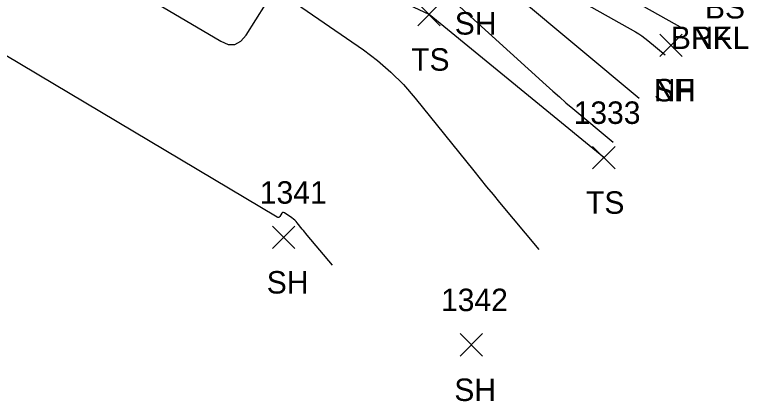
# Model space of a CAD drawing. Extents: x 1592612 to 1596497, y 111838 to 113741.
# Drawn here: x 1592923.4 to 1592988.7, y 113203.6 to 113238 of the extents above; entities that cross this region are included whole.
import ezdxf

# ---------------------------------------------------------------- set-up
doc = ezdxf.new("R2010")
doc.units = 0
for name, color, linetype in [('L_A', 7, 'Continuous'), ('L_I', 7, 'Continuous'), ('L_TIC', 7, 'Continuous'), ('LELB', 7, 'Continuous'), ('LSOGCMA', 7, 'Continuous'), ('LSOGCMI', 7, 'Continuous')]:
    doc.layers.add(name, color=color, linetype=linetype)

msp = doc.modelspace()

# ---------------------------------------------------------------- linework, layer by layer
at = {"layer": 'L_TIC'}
for points in [[(1592959.292, 113236.985), (1592961.292, 113238.985)], [(1592961.292, 113236.985), (1592959.292, 113238.985)], [(1592980.827, 113234.253), (1592982.827, 113236.253)], [(1592982.827, 113234.253), (1592980.827, 113236.253)], [(1592980.827, 113234.253), (1592982.827, 113236.253)], [(1592982.827, 113234.253), (1592980.827, 113236.253)], [(1592974.857, 113224.25), (1592976.857, 113226.25)], [(1592976.857, 113224.25), (1592974.857, 113226.25)], [(1592946.356, 113217.15), (1592948.356, 113219.15)], [(1592948.356, 113217.15), (1592946.356, 113219.15)], [(1592963.052, 113207.585), (1592965.052, 113209.585)], [(1592965.052, 113207.585), (1592963.052, 113209.585)]]:
    msp.add_lwpolyline(points, dxfattribs=at)
at = {"layer": 'LELB'}
msp.add_lwpolyline([(1592975.857, 113225.25), (1592960.292, 113237.985), (1592946.461, 113244.481), (1592940.546, 113245.09), (1592929.666, 113258.516), (1592911.285, 113250.895)], dxfattribs=at)
at = {"layer": 'LSOGCMA'}
msp.add_lwpolyline([(1592972.797, 113239.766), (1592978.672, 113236.445), (1592978.96, 113236.274), (1592979.239, 113236.09), (1592979.509, 113235.894), (1592979.771, 113235.685), (1592981.314, 113234.393)], dxfattribs=at)
at = {"layer": 'LSOGCMI'}
for points in [[(1592934.036, 113240.199), (1592941.759, 113235.608), (1592942.422, 113235.332), (1592943.019, 113235.33), (1592943.55, 113235.604), (1592944.015, 113236.152), (1592945.741, 113238.894)], [(1592947.937, 113239.344), (1592954.446, 113234.839), (1592955.714, 113233.893), (1592956.905, 113232.863), (1592958.017, 113231.749), (1592959.052, 113230.552), (1592964.269, 113224.062), (1592964.839, 113223.356), (1592965.413, 113222.652), (1592965.991, 113221.952), (1592966.572, 113221.255), (1592970.07, 113217.08)], [(1592978.996, 113230.51), (1592968.068, 113239.652)], [(1592982.888, 113236.734), (1592977.946, 113239.527)], [(1592962.382, 113239.254), (1592970.724, 113231.689), (1592971.305, 113231.167), (1592971.892, 113230.651), (1592972.484, 113230.14), (1592973.081, 113229.636), (1592976.678, 113226.626)], [(1592951.691, 113215.666), (1592949.442, 113218.351), (1592949.332, 113218.483), (1592949.223, 113218.616), (1592949.114, 113218.749), (1592949.006, 113218.883), (1592948.565, 113219.432), (1592948.458, 113219.555), (1592948.343, 113219.67), (1592948.22, 113219.777), (1592948.089, 113219.875), (1592947.416, 113220.34), (1592947.35, 113220.373), (1592947.29, 113220.376), (1592947.237, 113220.35), (1592947.189, 113220.294), (1592947.011, 113220.01), (1592946.963, 113219.954), (1592946.908, 113219.925), (1592946.846, 113219.925), (1592946.777, 113219.954), (1592918.254, 113236.909)]]:
    msp.add_lwpolyline(points, dxfattribs=at)

# ---------------------------------------------------------------- texts
at = {"layer": 'L_A'}
for s, p in [('BS', (1592984.849, 113237.634)), ('SH', (1592962.58, 113236.199)), ('BRKL', (1592981.816, 113234.92)), ('NF', (1592983.651, 113234.92)), ('TS', (1592958.701, 113232.985)), ('SH', (1592980.315, 113230.253)), ('NF', (1592980.308, 113230.253)), ('TS', (1592974.266, 113220.25)), ('SH', (1592945.844, 113213.15)), ('SH', (1592962.541, 113203.585))]:
    msp.add_text(s, height=2, dxfattribs=at).set_placement(p)
at = {"layer": 'L_I'}
for s, p in [('1333', (1592973.164, 113228.25)), ('1341', (1592945.23, 113221.15)), ('1342', (1592961.359, 113211.585))]:
    msp.add_text(s, height=2, dxfattribs=at).set_placement(p)

doc.saveas('drawing.dxf')
